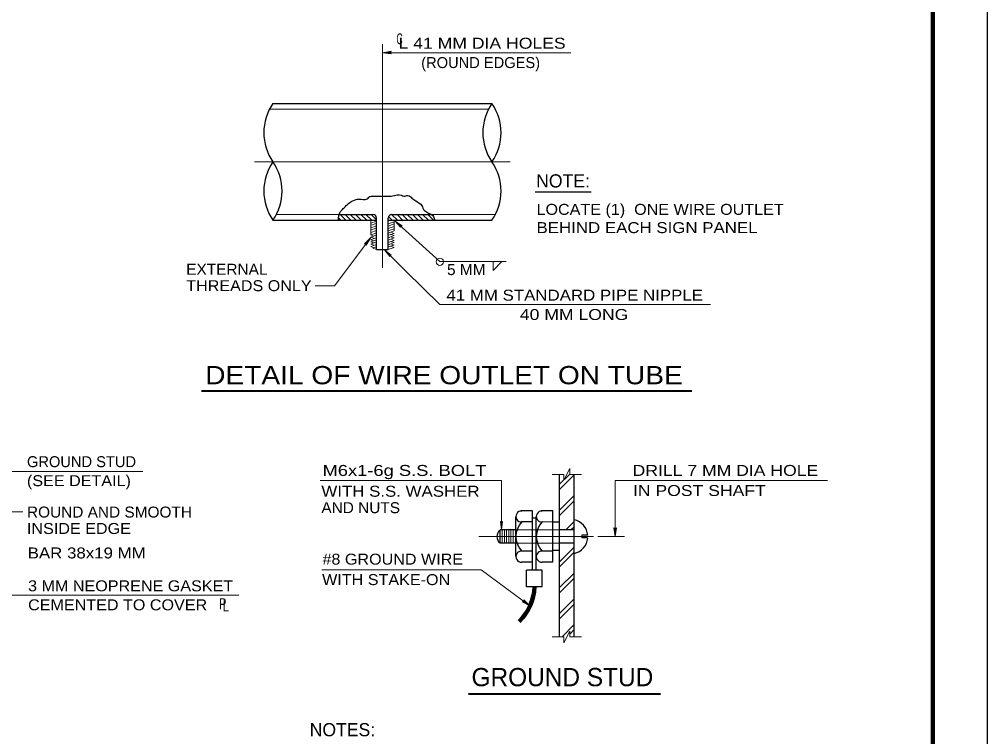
# Model space of a CAD drawing. Extents: x 312601.858 to 312602.699, y 144420.109 to 144420.704.
# Drawn here: x 312602.4337 to 312602.6988, y 144420.3244 to 144420.5208 of the extents above; entities that cross this region are included whole.
import ezdxf
from ezdxf.enums import TextEntityAlignment as Align

# ---------------------------------------------------------------- set-up
doc = ezdxf.new("R2010")
doc.units = 0
doc.header["$LTSCALE"] = 0.0012
doc.linetypes.add('LONG_DASH_SHORT_DASH', pattern=[9.9, 6, -1.2, 1.5, -1.2])
doc.linetypes.add('LONG_DASHED', pattern=[7.5, 6, -1.5])
for name, color, linetype, lineweight in [('1', 7, 'Continuous', 25), ('2', 7, 'Continuous', 25), ('39', 7, 'Continuous', 13)]:
    doc.layers.add(name, color=color, linetype=linetype, lineweight=lineweight)

msp = doc.modelspace()

# ---------------------------------------------------------------- hatches: boundary and pattern name
at = {"layer": '39'}
for points in [[(312602.5353, 144420.5117), (312602.5355, 144420.5114), (312602.5331, 144420.5117), (312602.5355, 144420.5121)], [(312602.5286, 144420.4594), (312602.5282, 144420.4594), (312602.5299, 144420.4611), (312602.5287, 144420.459)], [(312602.5968, 144420.3814), (312602.5972, 144420.3816), (312602.5968, 144420.3792), (312602.5965, 144420.3816)], [(312602.5718, 144420.3615), (312602.5718, 144420.3619), (312602.5735, 144420.3602), (312602.5714, 144420.3613)]]:
    msp.add_hatch(color=256, dxfattribs=at).paths.add_polyline_path(points)

# ---------------------------------------------------------------- linework, layer by layer
at = {"layer": '1', "lineweight": 13}
for p, q in [((312602.5331, 144420.514), (312602.5331, 144420.5028)), ((312602.5331, 144420.5117), (312602.5847, 144420.5117)), ((312602.5217, 144420.4658), (312602.5212, 144420.4664)), ((312602.5231, 144420.4658), (312602.5215, 144420.4674)), ((312602.5245, 144420.4658), (312602.5229, 144420.4674)), ((312602.5259, 144420.4658), (312602.5243, 144420.4674)), ((312602.5273, 144420.4658), (312602.5257, 144420.4674)), ((312602.5288, 144420.4658), (312602.5272, 144420.4674)), ((312602.5302, 144420.4658), (312602.5286, 144420.4674)), ((312602.5299, 144420.4658), (312602.5299, 144420.4618)), ((312602.5299, 144420.465), (312602.5315, 144420.4656)), ((312602.5315, 144420.4659), (312602.53, 144420.4674)), ((312602.5347, 144420.4648), (312602.5363, 144420.4654)), ((312602.5358, 144420.4658), (312602.5348, 144420.4668)), ((312602.5372, 144420.4658), (312602.5356, 144420.4674)), ((312602.5363, 144420.4658), (312602.5363, 144420.4629)), ((312602.5488, 144420.4545), (312602.5366, 144420.4656)), ((312602.5388, 144420.4657), (312602.5372, 144420.4673)), ((312602.5401, 144420.4658), (312602.5385, 144420.4674)), ((312602.5415, 144420.4658), (312602.5399, 144420.4674)), ((312602.5429, 144420.4658), (312602.5413, 144420.4674)), ((312602.5443, 144420.4658), (312602.5427, 144420.4674)), ((312602.5457, 144420.4658), (312602.5441, 144420.4674)), ((312602.5471, 144420.4658), (312602.5455, 144420.4674)), ((312602.5299, 144420.4644), (312602.5315, 144420.465)), ((312602.5299, 144420.4637), (312602.5315, 144420.4643)), ((312602.5299, 144420.4631), (312602.5315, 144420.4637)), ((312602.5299, 144420.4625), (312602.5315, 144420.463)), ((312602.5347, 144420.4642), (312602.5363, 144420.4648)), ((312602.5347, 144420.4636), (312602.5363, 144420.4641)), ((312602.5347, 144420.4629), (312602.5363, 144420.4635)), ((312602.5347, 144420.4623), (312602.5363, 144420.4629)), ((312602.5354, 144420.4626), (312602.5363, 144420.4622)), ((312602.5299, 144420.4611), (312602.52, 144420.4479)), ((312602.5299, 144420.4618), (312602.5315, 144420.4624)), ((312602.5299, 144420.4612), (312602.5315, 144420.4618)), ((312602.5299, 144420.4618), (312602.5308, 144420.4615)), ((312602.5299, 144420.4612), (312602.5308, 144420.4609)), ((312602.5299, 144420.4605), (312602.5315, 144420.4611)), ((312602.5299, 144420.4599), (312602.5315, 144420.4605)), ((312602.5299, 144420.4605), (312602.5308, 144420.4602)), ((312602.5299, 144420.4593), (312602.5315, 144420.4599)), ((312602.5299, 144420.4599), (312602.5308, 144420.4596)), ((312602.5347, 144420.4617), (312602.5363, 144420.4622)), ((312602.5347, 144420.461), (312602.5363, 144420.4616)), ((312602.5347, 144420.4604), (312602.5363, 144420.461)), ((312602.5347, 144420.4597), (312602.5363, 144420.4603)), ((312602.5354, 144420.4619), (312602.5363, 144420.4616)), ((312602.5354, 144420.4613), (312602.5363, 144420.461)), ((312602.5354, 144420.4606), (312602.5363, 144420.4603)), ((312602.5354, 144420.46), (312602.5363, 144420.4597)), ((312602.5299, 144420.4593), (312602.5308, 144420.459)), ((312602.5299, 144420.4586), (312602.5315, 144420.4592)), ((312602.5299, 144420.4586), (312602.5308, 144420.4583)), ((312602.5305, 144420.4582), (312602.5315, 144420.4586)), ((312602.5305, 144420.4582), (312602.5315, 144420.4578)), ((312602.5337, 144420.4577), (312602.5396, 144420.4518)), ((312602.5347, 144420.4591), (312602.5363, 144420.4597)), ((312602.5347, 144420.4585), (312602.5363, 144420.459)), ((312602.5347, 144420.4578), (312602.5363, 144420.4584)), ((312602.5354, 144420.4594), (312602.5363, 144420.459)), ((312602.5354, 144420.4587), (312602.5363, 144420.4584)), ((312602.5488, 144420.4545), (312602.567, 144420.4545)), ((312602.5396, 144420.4518), (312602.5488, 144420.4427)), ((312602.52, 144420.4479), (312602.5147, 144420.4479)), ((312602.5488, 144420.4427), (312602.6229, 144420.4427)), ((312602.4127, 144420.397), (312602.4675, 144420.397)), ((312602.5828, 144420.3946), (312602.5844, 144420.3978)), ((312602.5844, 144420.3962), (312602.5844, 144420.3978)), ((312602.5657, 144420.3945), (312602.5161, 144420.3945)), ((312602.5657, 144420.381), (312602.5657, 144420.3945)), ((312602.5828, 144420.3962), (312602.5796, 144420.3962)), ((312602.5816, 144420.3935), (312602.5843, 144420.3962)), ((312602.5816, 144420.3921), (312602.5856, 144420.3961)), ((312602.5828, 144420.3946), (312602.5828, 144420.3962)), ((312602.5876, 144420.3962), (312602.5844, 144420.3962)), ((312602.5968, 144420.3792), (312602.5968, 144420.3945)), ((312602.655, 144420.3945), (312602.5968, 144420.3945)), ((312602.5816, 144420.3864), (312602.5856, 144420.3904)), ((312602.5816, 144420.385), (312602.5856, 144420.389)), ((312602.4277, 144420.386), (312602.4347, 144420.386)), ((312602.5696, 144420.38), (312602.5696, 144420.3836)), ((312602.5833, 144420.381), (312602.5856, 144420.3833)), ((312602.5659, 144420.3774), (312602.5659, 144420.381)), ((312602.5665, 144420.3774), (312602.5665, 144420.381)), ((312602.5671, 144420.3774), (312602.5671, 144420.381)), ((312602.5677, 144420.3774), (312602.5677, 144420.381)), ((312602.5683, 144420.3774), (312602.5683, 144420.381)), ((312602.5689, 144420.3774), (312602.5689, 144420.381)), ((312602.5847, 144420.381), (312602.5856, 144420.3819)), ((312602.5877, 144420.3788), (312602.5877, 144420.3796)), ((312602.5994, 144420.3792), (312602.5921, 144420.3792)), ((312602.5816, 144420.3723), (312602.5856, 144420.3763)), ((312602.5816, 144420.3709), (312602.5856, 144420.3749)), ((312602.5601, 144420.3701), (312602.5165, 144420.3701)), ((312602.5601, 144420.3701), (312602.5735, 144420.3602)), ((312602.5816, 144420.3652), (312602.5856, 144420.3692)), ((312602.5816, 144420.3638), (312602.5856, 144420.3678)), ((312602.4308, 144420.3631), (312602.4938, 144420.3631)), ((312602.5816, 144420.3581), (312602.5856, 144420.3621)), ((312602.5816, 144420.3567), (312602.5856, 144420.3607)), ((312602.5823, 144420.3517), (312602.5856, 144420.3551)), ((312602.5828, 144420.3517), (312602.5796, 144420.3517)), ((312602.5828, 144420.3501), (312602.5844, 144420.3533)), ((312602.5828, 144420.3501), (312602.5828, 144420.3517)), ((312602.5844, 144420.3525), (312602.5856, 144420.3537)), ((312602.5844, 144420.3517), (312602.5844, 144420.3533)), ((312602.5876, 144420.3517), (312602.5844, 144420.3517))]:
    msp.add_line(p, q, dxfattribs=at)
at = {"layer": '1', "linetype": 'LONG_DASH_SHORT_DASH', "lineweight": 13}
for p, q in [((312602.5331, 144420.5022), (312602.5331, 144420.5028)), ((312602.5331, 144420.4528), (312602.5331, 144420.5022)), ((312602.4981, 144420.4818), (312602.5681, 144420.4818)), ((312602.5909, 144420.3792), (312602.5595, 144420.3792))]:
    msp.add_line(p, q, dxfattribs=at)
at = {"layer": '1'}
for p, q in [((312602.5031, 144420.4978), (312602.5631, 144420.4978)), ((312602.5749, 144420.4736), (312602.5903, 144420.4736)), ((312602.5031, 144420.4658), (312602.5315, 144420.4658)), ((312602.5212, 144420.4674), (312602.5305, 144420.4674)), ((312602.5315, 144420.4578), (312602.5315, 144420.4664)), ((312602.5347, 144420.4578), (312602.5347, 144420.4664)), ((312602.5347, 144420.4658), (312602.5631, 144420.4658)), ((312602.5357, 144420.4674), (312602.5466, 144420.4674)), ((312602.5315, 144420.4578), (312602.5347, 144420.4578)), ((312602.5816, 144420.3517), (312602.5816, 144420.3962)), ((312602.5856, 144420.3517), (312602.5856, 144420.3962)), ((312602.5742, 144420.3862), (312602.5711, 144420.3862)), ((312602.5742, 144420.37), (312602.5742, 144420.3862)), ((312602.5798, 144420.3862), (312602.5766, 144420.3862)), ((312602.5798, 144420.3722), (312602.5798, 144420.3862)), ((312602.5696, 144420.3738), (312602.5696, 144420.3846)), ((312602.5742, 144420.3832), (312602.5712, 144420.3832)), ((312602.5752, 144420.3842), (312602.5742, 144420.3842)), ((312602.5752, 144420.37), (312602.5752, 144420.3846)), ((312602.5653, 144420.3774), (312602.5653, 144420.381)), ((312602.5696, 144420.381), (312602.5653, 144420.381)), ((312602.5856, 144420.381), (312602.5816, 144420.381)), ((312602.5893, 144420.3796), (312602.5877, 144420.3796)), ((312602.5893, 144420.3788), (312602.5877, 144420.3788)), ((312602.5696, 144420.3774), (312602.5653, 144420.3774)), ((312602.5742, 144420.3752), (312602.5712, 144420.3752)), ((312602.5798, 144420.3752), (312602.5768, 144420.3752)), ((312602.5816, 144420.3754), (312602.5798, 144420.3754)), ((312602.5856, 144420.3774), (312602.5816, 144420.3774)), ((312602.5742, 144420.3722), (312602.5712, 144420.3722)), ((312602.5768, 144420.37), (312602.5726, 144420.37)), ((312602.5798, 144420.3722), (312602.5768, 144420.3722)), ((312602.5768, 144420.3654), (312602.5768, 144420.37))]:
    msp.add_line(p, q, dxfattribs=at)
at = {"layer": '1', "linetype": 'LONG_DASHED', "lineweight": 13}
for p, q in [((312602.5022, 144420.4962), (312602.5621, 144420.4962)), ((312602.5041, 144420.4674), (312602.5212, 144420.4674)), ((312602.5466, 144420.4674), (312602.564, 144420.4674)), ((312602.5816, 144420.381), (312602.5696, 144420.381)), ((312602.5816, 144420.3774), (312602.5696, 144420.3774))]:
    msp.add_line(p, q, dxfattribs=at)
at = {"layer": '1', "lineweight": 40}
for p, q in [((312602.4836, 144420.4191), (312602.6178, 144420.4191)), ((312602.5567, 144420.3361), (312602.6092, 144420.3361))]:
    msp.add_line(p, q, dxfattribs=at)
at = {"layer": '1', "lineweight": 13}
for points in [[(312602.5381, 144420.4639), (312602.5366, 144420.4656), (312602.5385, 144420.4643), (312602.5381, 144420.4642)], [(312602.5351, 144420.4559), (312602.5337, 144420.4577), (312602.5355, 144420.4563), (312602.5351, 144420.4563)], [(312602.566, 144420.3833), (312602.5657, 144420.381), (312602.5654, 144420.3833), (312602.5657, 144420.383)]]:
    msp.add_lwpolyline(points, close=True, dxfattribs=at)
msp.add_lwpolyline([(312602.5634, 144420.4545), (312602.5634, 144420.4521), (312602.5658, 144420.4545)], dxfattribs=at)
at = {"layer": '1'}
for points in [[(312602.5815, 144420.3831), (312602.5797, 144420.3831), (312602.5768, 144420.3832)], [(312602.5768, 144420.3654), (312602.5726, 144420.3654), (312602.5726, 144420.37)]]:
    msp.add_lwpolyline(points, dxfattribs=at)
at = {"layer": '1', "lineweight": 13}
msp.add_circle((312602.548842, 144420.454465), 0.000999, dxfattribs=at)
at = {"layer": '1'}
for centre, radius, start, end in [((312602.514684, 144420.489796), 0.014037, 145.23465, 214.70805), ((312602.574628, 144420.489796), 0.014037, 145.29195, 214.70805), ((312602.55155, 144420.489796), 0.014037, 325.29195, 34.70805), ((312602.514684, 144420.473811), 0.014037, 145.29195, 214.70805), ((312602.491606, 144420.473811), 0.014037, 325.29195, 34.70805), ((312602.55155, 144420.473811), 0.014037, 325.29195, 34.70805), ((312602.53052, 144420.466418), 0.000999, 0, 90), ((312602.535715, 144420.466418), 0.000999, 90, 180), ((312602.571151, 144420.384683), 0.001502, 86.30478, 273.69522), ((312602.576746, 144420.384683), 0.001502, 86.30478, 273.69522), ((312602.575444, 144420.379188), 0.005795, 136.39718, 223.60282), ((312602.581039, 144420.379188), 0.005795, 136.39718, 223.60282), ((312602.584626, 144420.379188), 0.004705, 4.87231, 77.62277), ((312602.566877, 144420.379188), 0.002423, 132.07502, 227.92498), ((312602.584626, 144420.379188), 0.004705, 282.37723, 355.12769), ((312602.571151, 144420.373693), 0.001502, 86.30478, 273.69522), ((312602.576746, 144420.373693), 0.001502, 86.30478, 273.69522)]:
    msp.add_arc(centre, radius, start, end, dxfattribs=at)
at = {"layer": '1', "lineweight": 140}
msp.add_arc((312602.56053, 144420.366015), 0.014228, 315.00003, 357.52779, dxfattribs=at)
at = {"layer": '1'}
msp.add_spline([(312602.5211, 144420.4659), (312602.5212, 144420.4672), (312602.5219, 144420.4685), (312602.5229, 144420.4695), (312602.5242, 144420.4707), (312602.5247, 144420.471), (312602.5267, 144420.4716), (312602.5289, 144420.4717), (312602.53, 144420.4724), (312602.5303, 144420.4724), (312602.5317, 144420.4724), (312602.5345, 144420.4724), (312602.5359, 144420.4725), (312602.5383, 144420.4727), (312602.539, 144420.4724), (312602.5401, 144420.4726), (312602.5412, 144420.4719), (312602.5423, 144420.4711), (312602.5439, 144420.4698), (312602.5446, 144420.4685), (312602.5452, 144420.4681), (312602.5457, 144420.4678), (312602.5469, 144420.4671), (312602.5474, 144420.466)], degree=3, dxfattribs=at)
at = {"layer": '39', "lineweight": 25}
msp.add_line((312602.6988, 144420.1095), (312602.6988, 144420.7035), dxfattribs=at)
msp.add_line((312602.6988, 144420.1095), (312602.6988, 144420.7035), dxfattribs=at)
msp.add_line((312602.6988, 144420.1095), (312602.6988, 144420.7035), dxfattribs=at)
at = {"layer": '39', "lineweight": 158}
msp.add_line((312602.6838, 144420.1247), (312602.6838, 144420.6645), dxfattribs=at)
at = {"layer": '39'}
for points in [[(312602.5353, 144420.5117), (312602.5355, 144420.5114), (312602.5331, 144420.5117), (312602.5355, 144420.5121)], [(312602.5286, 144420.4594), (312602.5282, 144420.4594), (312602.5299, 144420.4611), (312602.5287, 144420.459)], [(312602.5968, 144420.3814), (312602.5972, 144420.3816), (312602.5968, 144420.3792), (312602.5965, 144420.3816)], [(312602.5718, 144420.3615), (312602.5718, 144420.3619), (312602.5735, 144420.3602), (312602.5714, 144420.3613)]]:
    msp.add_lwpolyline(points, close=True, dxfattribs=at)

# ---------------------------------------------------------------- texts
at = {"layer": '1'}
msp.add_text('(ROUND EDGES)', height=0.003, dxfattribs=at).set_placement((312602.56, 144420.5075), align=Align.CENTER)
for s, width, p in [('LOCATE (1)  ONE WIRE OUTLET', 1.1, (312602.5753, 144420.4673)), ('BEHIND EACH SIGN PANEL ', 1.15, (312602.5753, 144420.4623)), ('EXTERNAL', 1.05, (312602.4794, 144420.4509)), ('5 MM', 1.05, (312602.5508, 144420.4508)), ('THREADS ONLY', 1.1, (312602.4794, 144420.4464)), ('DRILL 7 MM DIA HOLE', 1.2, (312602.6016, 144420.3958)), ('(SEE DETAIL)', 1.1, (312602.4358, 144420.393)), ('IN POST SHAFT', 1.2, (312602.6017, 144420.3903)), ('ROUND AND SMOOTH', 1.05, (312602.4358, 144420.3844)), ('INSIDE EDGE', 1.1, (312602.4358, 144420.3799)), ('BAR 38x19 MM', 1.15, (312602.436, 144420.3732)), ('#8 GROUND WIRE', 1.1, (312602.5167, 144420.3715)), ('3 MM NEOPRENE GASKET', 1.1, (312602.4361, 144420.3642)), ('WITH STAKE-ON', 1.1, (312602.5166, 144420.3659)), ('CEMENTED TO COVER ', 1.1, (312602.4361, 144420.359))]:
    msp.add_text(s, height=0.003, dxfattribs=dict(at, width=width)).set_placement(p)
for s, width, p in [('41 MM STANDARD PIPE NIPPLE', 1.15, (312602.58575, 144420.4438)), ('40 MM LONG ', 1.2, (312602.58625, 144420.4385)), ('P', 0.75, (312602.4894, 144420.3593)), ('L', 0.75, (312602.49025, 144420.3587))]:
    msp.add_text(s, height=0.003, dxfattribs=dict(at, width=width)).set_placement(p, align=Align.CENTER)
msp.add_text('GROUND STUD', height=0.003, dxfattribs=at).set_placement((312602.4358, 144420.3982))
at = {"layer": '2'}
for s, width, p in [('C', 0.6, (312602.5378, 144420.514)), ('L 41 MM DIA HOLES', 1.2, (312602.5604, 144420.5128)), ('M6x1-6g S.S. BOLT', 1.25, (312602.53915, 144420.3958))]:
    msp.add_text(s, height=0.003, dxfattribs=dict(at, width=width)).set_placement(p, align=Align.CENTER)
for s, height, p in [('NOTE:', 0.0036, (312602.5752, 144420.4748)), ('GROUND STUD', 0.005, (312602.5575, 144420.3382)), ('NOTES:', 0.0036, (312602.5132, 144420.3245))]:
    msp.add_text(s, height=height, dxfattribs=at).set_placement(p)
at = {"layer": '2', "width": 1.15}
msp.add_text('DETAIL OF WIRE OUTLET ON TUBE', height=0.005, dxfattribs=at).set_placement((312602.4846, 144420.4209))
at = {"layer": '39'}
for s, width, p in [('WITH S.S. WASHER', 1.15, (312602.5164, 144420.3901)), ('AND NUTS', 1.05, (312602.5164, 144420.3856))]:
    msp.add_text(s, height=0.003, dxfattribs=dict(at, width=width)).set_placement(p)

doc.saveas('drawing.dxf')
